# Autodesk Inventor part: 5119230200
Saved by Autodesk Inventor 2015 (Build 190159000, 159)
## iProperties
Created: 2020-07
Part Number: 5119230200
Checked By: TraceParts S.A.
Material: Generic
Catalog Web Link: www.traceparts.com
Document SubType Name: Modeling
Designer: TraceParts
Density: 1 g/cm^3
Appearance: Default
Company: TraceParts S.A.
Author: TraceParts
REFERENCE: 5119230200
DESIGN: HIB-1250 P 1,1KW (230V 50HZ) - 5119230200
SUPPLIER: Soler & Palau
TraceParts.PartNumber: 10-20122018-119595
TraceParts.PartTitle: HIB-P/HIT-P
TraceParts.InstanceId: 10-20122018-1195958X0YNT6BWEFR1L8GEW5J7KLWH
TraceParts.PartStatus: Published
TraceParts.PartVersion: 1.0.2
TRACEPARTS: TRACEPARTS
TraceParts.PartLanguage: en
TraceParts.ClassPath: SOLER_PALAU:10-20122018-119595
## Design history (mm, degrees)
feature "5119230200"
body "Solid1"
